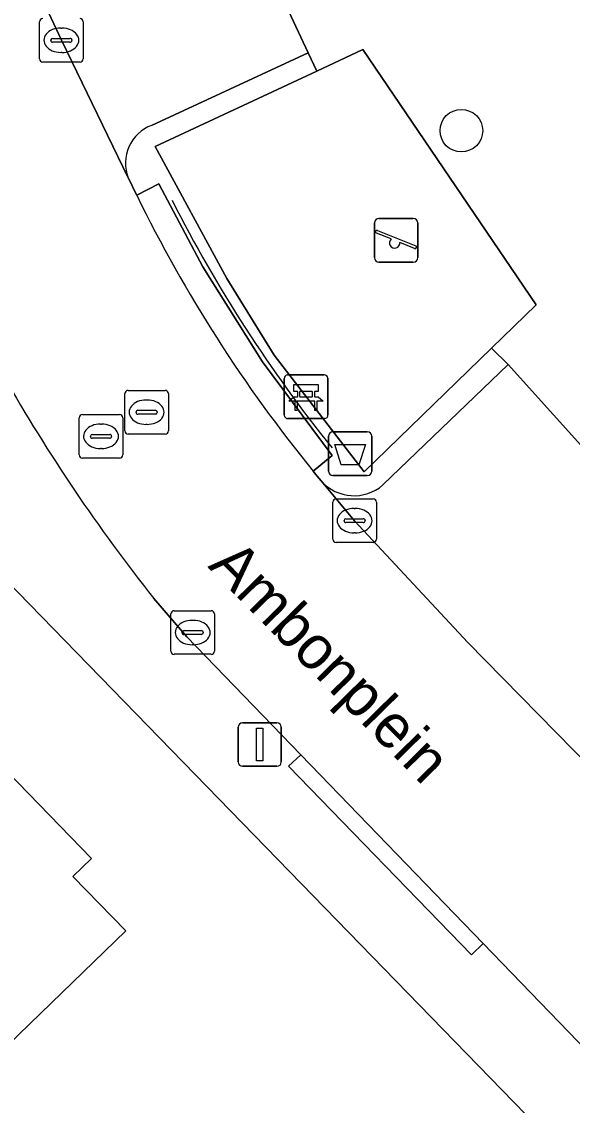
# Model space of a CAD drawing. Extents: x 162879 to 165540, y 384011 to 385181.
# Drawn here: x 163881.82 to 163894.44, y 384275.54 to 384300.4 of the extents above; entities that cross this region are included whole.
import ezdxf

# ---------------------------------------------------------------- set-up
doc = ezdxf.new("R2010")
doc.units = 0
for name, color, linetype in [('IMGEO_Afvalbak', 7, 'Continuous'), ('IMGEO_Bank', 7, 'Continuous'), ('IMGEO_Boom', 7, 'Continuous'), ('IMGEO_Erf', 7, 'Continuous'), ('IMGEO_Groenvoorziening', 7, 'Continuous'), ('IMGEO_Haag', 7, 'Continuous'), ('IMGEO_Hek', 7, 'Continuous'), ('IMGEO_Kolk', 7, 'Continuous'), ('IMGEO_Lichtmast', 7, 'Continuous'), ('IMGEO_Openbare_ruimte_label', 7, 'Continuous'), ('IMGEO_Pand', 7, 'Continuous'), ('IMGEO_Parkeervlak_open', 7, 'Continuous'), ('IMGEO_Rijbaan_lokaal_gesloten', 7, 'Continuous'), ('IMGEO_Rioolput', 7, 'Continuous'), ('IMGEO_Speelvoorziening', 7, 'Continuous'), ('IMGEO_Terreindeel_onvherhard', 7, 'Continuous'), ('IMGEO_Voetpad_open', 7, 'Continuous')]:
    doc.layers.add(name, color=color, linetype=linetype)

msp = doc.modelspace()

# ---------------------------------------------------------------- linework, layer by layer
at = {"layer": 'IMGEO_Afvalbak'}
for p, q in [((163888.855, 384290.09), (163888.855, 384290.89)), ((163888.855, 384290.89), (163888.855, 384290.09)), ((163888.955, 384290.99), (163889.745, 384290.99)), ((163889.745, 384290.99), (163888.955, 384290.99)), ((163889.845, 384290.89), (163889.845, 384290.09)), ((163889.845, 384290.09), (163889.845, 384290.89)), ((163889.745, 384289.99), (163888.955, 384289.99)), ((163888.955, 384289.99), (163889.745, 384289.99))]:
    msp.add_line(p, q, dxfattribs=at)
msp.add_lwpolyline([(163888.998, 384290.704), (163889.702, 384290.704), (163889.553, 384290.234), (163889.147, 384290.234), (163888.998, 384290.704)], dxfattribs=at)
for centre, start, end in [((163888.955, 384290.89), 90, 180), ((163888.955, 384290.89), 90, 180), ((163889.745, 384290.89), 0, 90), ((163889.745, 384290.89), 360, 90), ((163888.955, 384290.09), 180, 270), ((163888.955, 384290.09), 180, 270), ((163889.745, 384290.09), 270, 0), ((163889.745, 384290.09), 270, 0)]:
    msp.add_arc(centre, 0.1, start, end, dxfattribs=at)
at = {"layer": 'IMGEO_Bank'}
for p, q in [((163887.916, 384292.297), (163888.757, 384292.297)), ((163888.757, 384292.297), (163887.916, 384292.297)), ((163887.841, 384291.372), (163887.841, 384292.213)), ((163887.841, 384292.213), (163887.841, 384291.372)), ((163888.841, 384292.222), (163888.841, 384291.381)), ((163888.841, 384291.381), (163888.841, 384292.222)), ((163888.15, 384291.803), (163888.15, 384291.909)), ((163888.194, 384291.909), (163888.194, 384291.803)), ((163888.482, 384291.915), (163888.2, 384291.915)), ((163888.2, 384291.797), (163888.482, 384291.797)), ((163888.488, 384291.803), (163888.488, 384291.909)), ((163888.532, 384291.909), (163888.532, 384291.803)), ((163888.538, 384291.695), (163888.145, 384291.695)), ((163888.766, 384291.297), (163887.925, 384291.297)), ((163887.925, 384291.297), (163888.766, 384291.297))]:
    msp.add_line(p, q, dxfattribs=at)
for points in [[(163888.144, 384291.915), (163888.058, 384291.915), (163888.058, 384292.076), (163888.621, 384292.076), (163888.621, 384291.915), (163888.538, 384291.915)], [(163888.088, 384291.695), (163887.946, 384291.695), (163888.058, 384291.797), (163888.144, 384291.797)], [(163888.538, 384291.797), (163888.621, 384291.797), (163888.733, 384291.695), (163888.594, 384291.695)], [(163888.138, 384291.688), (163888.138, 384291.481), (163888.095, 384291.481), (163888.095, 384291.688)], [(163888.588, 384291.688), (163888.588, 384291.481), (163888.544, 384291.481), (163888.544, 384291.688)]]:
    msp.add_lwpolyline(points, dxfattribs=at)
for centre, radius, start, end in [((163887.919, 384292.219), 0.0779, 92.4484, 184.2845), ((163887.919, 384292.219), 0.0779, 92.4484, 184.2845), ((163888.763, 384292.219), 0.0779, 2.4484, 94.2845), ((163888.763, 384292.219), 0.0779, 2.4484, 94.2845), ((163888.143, 384291.908), 0.00671, 2.8957, 87.1043), ((163888.143, 384291.804), 0.00671, 272.8957, 357.1043), ((163888.2, 384291.908), 0.00671, 92.8957, 177.1043), ((163888.2, 384291.804), 0.00671, 182.8957, 267.1043), ((163888.482, 384291.908), 0.00671, 2.8957, 87.1043), ((163888.482, 384291.804), 0.00671, 272.8957, 357.1043), ((163888.539, 384291.908), 0.00671, 92.8957, 177.1043), ((163888.539, 384291.804), 0.00671, 182.8957, 267.1043), ((163888.088, 384291.688), 0.00671, 2.8957, 87.1043), ((163888.145, 384291.688), 0.00671, 92.8957, 177.1043), ((163888.537, 384291.688), 0.00671, 2.8957, 87.1043), ((163888.594, 384291.688), 0.00671, 92.8957, 177.1043), ((163887.919, 384291.375), 0.0779, 182.4484, 274.2845), ((163887.919, 384291.375), 0.0779, 182.4484, 274.2845), ((163888.763, 384291.375), 0.0779, 272.4484, 4.2845), ((163888.763, 384291.375), 0.0779, 272.4484, 4.2845)]:
    msp.add_arc(centre, radius, start, end, dxfattribs=at)
at = {"layer": 'IMGEO_Boom'}
msp.add_circle((163891.9, 384297.9), 0.489, dxfattribs=at)
at = {"layer": 'IMGEO_Erf'}
for points in [[(163899.33, 384269.205), (163862.239, 384307.377)], [(163852.36, 384301.956), (163854.02, 384301.957), (163856.929, 384300.707), (163859.847, 384299.453), (163861.001, 384298.26), (163864.034, 384301.194), (163868.122, 384296.969), (163871.022, 384293.972), (163870.6, 384293.562), (163871.811, 384292.314), (163867.394, 384288.028), (163869.463, 384285.896), (163871.58, 384283.715), (163875.993, 384287.998), (163877.197, 384286.756), (163877.627, 384287.173), (163880.526, 384284.185), (163883.421, 384281.202), (163882.999, 384280.792), (163884.207, 384279.548), (163879.797, 384275.268)]]:
    msp.add_lwpolyline(points, dxfattribs=at)
at = {"layer": 'IMGEO_Groenvoorziening'}
msp.add_lwpolyline([(163888.505, 384290.088), (163888.943, 384290.447), (163887.341, 384292.596), (163885.974, 384294.779), (163884.964, 384296.677), (163884.46, 384296.42)], dxfattribs=at)
msp.add_arc((163914.001, 384310.833), 32.87, 206.0082, 219.1342, dxfattribs=at)
at = {"layer": 'IMGEO_Haag'}
msp.add_lwpolyline([(163888.505, 384290.088), (163888.943, 384290.447), (163887.341, 384292.596), (163885.974, 384294.779), (163884.964, 384296.677), (163884.46, 384296.42)], dxfattribs=at)
msp.add_arc((163914.001, 384310.833), 32.87, 206.0082, 219.1342, dxfattribs=at)
at = {"layer": 'IMGEO_Hek'}
msp.add_arc((163914.208, 384310.967), 32.442, 206.8705, 218.8312, dxfattribs=at)
at = {"layer": 'IMGEO_Kolk'}
for p, q in [((163882.233, 384299.548), (163882.233, 384300.4)), ((163882.721, 384300.254), (163882.746, 384300.254)), ((163883.234, 384300.4), (163883.234, 384299.548)), ((163882.535, 384300.017), (163882.933, 384300.017)), ((163882.492, 384299.968), (163882.492, 384299.98)), ((163882.93, 384299.931), (163882.532, 384299.931)), ((163882.976, 384299.98), (163882.976, 384299.968)), ((163882.744, 384299.694), (163882.719, 384299.694)), ((163883.16, 384299.474), (163882.308, 384299.474)), ((163888.953, 384288.528), (163888.953, 384289.38)), ((163889.028, 384289.454), (163889.88, 384289.454)), ((163889.954, 384289.38), (163889.954, 384288.528)), ((163889.441, 384289.234), (163889.466, 384289.234)), ((163889.212, 384288.948), (163889.212, 384288.96)), ((163889.65, 384288.911), (163889.252, 384288.911)), ((163889.255, 384288.997), (163889.653, 384288.997)), ((163889.696, 384288.96), (163889.696, 384288.948)), ((163889.464, 384288.674), (163889.439, 384288.674)), ((163889.88, 384288.454), (163889.028, 384288.454)), ((163885.242, 384285.962), (163885.242, 384286.814)), ((163885.317, 384286.888), (163886.169, 384286.888)), ((163886.243, 384286.814), (163886.243, 384285.962)), ((163885.73, 384286.668), (163885.755, 384286.668)), ((163885.501, 384286.382), (163885.501, 384286.394)), ((163885.939, 384286.345), (163885.541, 384286.345)), ((163885.544, 384286.431), (163885.942, 384286.431)), ((163885.985, 384286.394), (163885.985, 384286.382)), ((163885.753, 384286.108), (163885.728, 384286.108)), ((163886.169, 384285.888), (163885.317, 384285.888))]:
    msp.add_line(p, q, dxfattribs=at)
for points in [[(163882.233, 384299.548), (163882.233, 384300.4)], [(163883.234, 384300.4), (163883.234, 384299.548)], [(163883.16, 384299.474), (163882.308, 384299.474)], [(163888.953, 384288.528), (163888.953, 384289.38)], [(163889.028, 384289.454), (163889.88, 384289.454)], [(163889.954, 384289.38), (163889.954, 384288.528)], [(163889.88, 384288.454), (163889.028, 384288.454)], [(163885.242, 384285.962), (163885.242, 384286.814)], [(163885.317, 384286.888), (163886.169, 384286.888)], [(163886.243, 384286.814), (163886.243, 384285.962)], [(163886.169, 384285.888), (163885.317, 384285.888)]]:
    msp.add_lwpolyline(points, dxfattribs=at)
for centre, radius, start, end in [((163882.31, 384300.398), 0.0765, 91.552, 178.448), ((163882.31, 384300.398), 0.0765, 91.552, 178.448), ((163883.158, 384300.398), 0.0765, 1.552, 88.448), ((163883.158, 384300.398), 0.0765, 1.552, 88.448), ((163882.532, 384299.977), 0.0403, 85.8775, 175.7526), ((163882.937, 384299.979), 0.0386, 1.7309, 96.639), ((163882.529, 384299.967), 0.0366, 178.938, 274.7102), ((163882.933, 384299.974), 0.043, 264.8664, 352.4533), ((163882.31, 384299.55), 0.0765, 181.552, 268.448), ((163882.31, 384299.55), 0.0765, 181.552, 268.448), ((163883.158, 384299.55), 0.0765, 271.552, 358.448), ((163883.158, 384299.55), 0.0765, 271.552, 358.448), ((163889.03, 384289.378), 0.0765, 91.552, 178.448), ((163889.03, 384289.378), 0.0765, 91.552, 178.448), ((163889.878, 384289.378), 0.0765, 1.552, 88.448), ((163889.878, 384289.378), 0.0765, 1.552, 88.448), ((163889.252, 384288.957), 0.0403, 85.8775, 175.7526), ((163889.249, 384288.947), 0.0366, 178.938, 274.7102), ((163889.653, 384288.954), 0.043, 264.8664, 352.4533), ((163889.657, 384288.959), 0.0386, 1.7309, 96.639), ((163889.03, 384288.53), 0.0765, 181.552, 268.448), ((163889.03, 384288.53), 0.0765, 181.552, 268.448), ((163889.878, 384288.53), 0.0765, 271.552, 358.448), ((163889.878, 384288.53), 0.0765, 271.552, 358.448), ((163885.319, 384286.812), 0.0765, 91.552, 178.448), ((163885.319, 384286.812), 0.0765, 91.552, 178.448), ((163886.167, 384286.812), 0.0765, 1.552, 88.448), ((163886.167, 384286.812), 0.0765, 1.552, 88.448), ((163885.541, 384286.391), 0.0403, 85.8775, 175.7526), ((163885.538, 384286.381), 0.0366, 178.938, 274.7102), ((163885.942, 384286.388), 0.043, 264.8664, 352.4533), ((163885.946, 384286.393), 0.0386, 1.7309, 96.639), ((163885.319, 384285.964), 0.0765, 181.552, 268.448), ((163885.319, 384285.964), 0.0765, 181.552, 268.448), ((163886.167, 384285.964), 0.0765, 271.552, 358.448), ((163886.167, 384285.964), 0.0765, 271.552, 358.448)]:
    msp.add_arc(centre, radius, start, end, dxfattribs=at)
for centre, major_axis, ratio, start_param, end_param in [((163882.72, 384299.974), (-0.387, 0.002), 0.722429, 4.712389, 7.853982), ((163882.745, 384299.974), (-0.39, 0.002), 0.717154, 1.570796, 4.712389), ((163889.44, 384288.954), (-0.387, 0.002), 0.722429, 4.712389, 7.853982), ((163889.465, 384288.954), (-0.39, 0.002), 0.717154, 1.570796, 4.712389), ((163885.729, 384286.388), (-0.387, 0.002), 0.722429, 4.712389, 7.853982), ((163885.754, 384286.388), (-0.39, 0.002), 0.717154, 1.570796, 4.712389)]:
    msp.add_ellipse(centre, major_axis=major_axis, ratio=ratio, start_param=start_param, end_param=end_param, dxfattribs=at)
at = {"layer": 'IMGEO_Lichtmast'}
for p, q in [((163886.783, 384283.419), (163886.783, 384284.219)), ((163886.783, 384284.219), (163886.783, 384283.419)), ((163886.883, 384284.319), (163887.673, 384284.319)), ((163887.673, 384284.319), (163886.883, 384284.319)), ((163887.773, 384284.219), (163887.773, 384283.419)), ((163887.773, 384283.419), (163887.773, 384284.219)), ((163887.673, 384283.319), (163886.883, 384283.319)), ((163886.883, 384283.319), (163887.673, 384283.319))]:
    msp.add_line(p, q, dxfattribs=at)
msp.add_lwpolyline([(163887.203, 384284.194), (163887.353, 384284.194), (163887.353, 384283.444), (163887.203, 384283.444), (163887.203, 384284.194)], dxfattribs=at)
for centre, start, end in [((163886.883, 384284.219), 90, 180), ((163886.883, 384284.219), 90, 180), ((163887.673, 384284.219), 0, 90), ((163887.673, 384284.219), 360, 90), ((163886.883, 384283.419), 180, 270), ((163886.883, 384283.419), 180, 270), ((163887.673, 384283.419), 270, 0), ((163887.673, 384283.419), 270, 0)]:
    msp.add_arc(centre, 0.1, start, end, dxfattribs=at)
at = {"layer": 'IMGEO_Pand'}
msp.add_lwpolyline([(163872.435, 384276.367), (163876.307, 384272.378), (163874.635, 384270.755), (163876.963, 384268.356), (163881.884, 384273.118), (163879.797, 384275.268), (163884.207, 384279.548), (163882.999, 384280.792), (163883.421, 384281.202), (163880.526, 384284.185)], close=True, dxfattribs=at)
at = {"layer": 'IMGEO_Parkeervlak_open'}
for points in [[(163884.802, 384298.021), (163888.388, 384299.683), (163882.043, 384313.266), (163878.44, 384311.595)], [(163877.096, 384312.046), (163878.002, 384310.066), (163882.733, 384299.973), (163884.265, 384296.82)], [(163898.767, 384280.751), (163901.634, 384283.506), (163895.053, 384290.227), (163892.97, 384292.54), (163890.101, 384289.773)], [(163888.687, 384289.866), (163889.454, 384288.953), (163892.052, 384286.156), (163897.301, 384280.799), (163898.746, 384279.314)]]:
    msp.add_lwpolyline(points, dxfattribs=at)
for centre, radius, start, end in [((163885.125, 384297.156), 0.923, 110.4568, 201.3617), ((163889.441, 384290.535), 1.008, 221.5633, 310.9107)]:
    msp.add_arc(centre, radius, start, end, dxfattribs=at)
at = {"layer": 'IMGEO_Rijbaan_lokaal_gesloten'}
for points in [[(163884.46, 384296.42), (163884.395, 384296.553), (163884.331, 384296.686), (163884.265, 384296.82), (163882.733, 384299.973), (163878.002, 384310.066), (163877.096, 384312.046), (163876.805, 384312.696)], [(163899.806, 384278.207), (163898.746, 384279.314), (163897.301, 384280.799), (163892.052, 384286.156), (163889.454, 384288.953), (163888.687, 384289.866), (163888.596, 384289.977), (163888.505, 384290.088)], [(163884.85, 384287.172), (163885.611, 384286.288), (163888.22, 384283.584), (163892.399, 384279.255), (163900.23, 384271.142), (163903.359, 384267.9), (163903.727, 384267.518), (163912.083, 384275.609), (163924.617, 384287.795), (163925.486, 384288.61)]]:
    msp.add_lwpolyline(points, dxfattribs=at)
for centre, radius, start, end in [((163914.001, 384310.833), 32.87, 206.0082, 219.1342), ((163916.349, 384312.121), 40.183, 209.6097, 218.3807)]:
    msp.add_arc(centre, radius, start, end, dxfattribs=at)
at = {"layer": 'IMGEO_Rioolput'}
for p, q in [((163884.186, 384291.016), (163884.186, 384291.868)), ((163884.261, 384291.942), (163885.113, 384291.942)), ((163885.187, 384291.868), (163885.187, 384291.016)), ((163884.674, 384291.722), (163884.699, 384291.722)), ((163883.141, 384290.464), (163883.141, 384291.316)), ((163883.216, 384291.39), (163884.068, 384291.39)), ((163884.142, 384291.316), (163884.142, 384290.464)), ((163884.445, 384291.436), (163884.445, 384291.448)), ((163884.883, 384291.399), (163884.485, 384291.399)), ((163884.488, 384291.485), (163884.886, 384291.485)), ((163884.929, 384291.448), (163884.929, 384291.436)), ((163883.629, 384291.17), (163883.654, 384291.17)), ((163884.697, 384291.162), (163884.672, 384291.162)), ((163883.4, 384290.884), (163883.4, 384290.896)), ((163883.838, 384290.847), (163883.44, 384290.847)), ((163883.443, 384290.933), (163883.841, 384290.933)), ((163883.884, 384290.896), (163883.884, 384290.884)), ((163885.113, 384290.942), (163884.261, 384290.942)), ((163883.652, 384290.61), (163883.627, 384290.61)), ((163884.068, 384290.39), (163883.216, 384290.39))]:
    msp.add_line(p, q, dxfattribs=at)
for points in [[(163884.186, 384291.016), (163884.186, 384291.868)], [(163884.261, 384291.942), (163885.113, 384291.942)], [(163885.187, 384291.868), (163885.187, 384291.016)], [(163883.141, 384290.464), (163883.141, 384291.316)], [(163883.216, 384291.39), (163884.068, 384291.39)], [(163884.142, 384291.316), (163884.142, 384290.464)], [(163885.113, 384290.942), (163884.261, 384290.942)], [(163884.068, 384290.39), (163883.216, 384290.39)]]:
    msp.add_lwpolyline(points, dxfattribs=at)
for centre, radius, start, end in [((163884.263, 384291.866), 0.0765, 91.552, 178.448), ((163884.263, 384291.866), 0.0765, 91.552, 178.448), ((163885.111, 384291.866), 0.0765, 1.552, 88.448), ((163885.111, 384291.866), 0.0765, 1.552, 88.448), ((163883.218, 384291.314), 0.0765, 91.552, 178.448), ((163883.218, 384291.314), 0.0765, 91.552, 178.448), ((163884.066, 384291.314), 0.0765, 1.552, 88.448), ((163884.066, 384291.314), 0.0765, 1.552, 88.448), ((163884.485, 384291.445), 0.0403, 85.8775, 175.7526), ((163884.482, 384291.435), 0.0366, 178.938, 274.7102), ((163884.886, 384291.442), 0.043, 264.8664, 352.4533), ((163884.89, 384291.447), 0.0386, 1.7309, 96.639), ((163883.44, 384290.893), 0.0403, 85.8775, 175.7526), ((163883.437, 384290.883), 0.0366, 178.938, 274.7102), ((163883.841, 384290.89), 0.043, 264.8664, 352.4533), ((163883.845, 384290.895), 0.0386, 1.7309, 96.639), ((163884.263, 384291.018), 0.0765, 181.552, 268.448), ((163884.263, 384291.018), 0.0765, 181.552, 268.448), ((163885.111, 384291.018), 0.0765, 271.552, 358.448), ((163885.111, 384291.018), 0.0765, 271.552, 358.448), ((163883.218, 384290.466), 0.0765, 181.552, 268.448), ((163883.218, 384290.466), 0.0765, 181.552, 268.448), ((163884.066, 384290.466), 0.0765, 271.552, 358.448), ((163884.066, 384290.466), 0.0765, 271.552, 358.448)]:
    msp.add_arc(centre, radius, start, end, dxfattribs=at)
for centre, major_axis, ratio, start_param, end_param in [((163884.673, 384291.442), (-0.387, 0.002), 0.722429, 4.712389, 7.853982), ((163884.698, 384291.442), (-0.39, 0.002), 0.717154, 1.570796, 4.712389), ((163883.628, 384290.89), (-0.387, 0.002), 0.722429, 4.712389, 7.853982), ((163883.653, 384290.89), (-0.39, 0.002), 0.717154, 1.570796, 4.712389)]:
    msp.add_ellipse(centre, major_axis=major_axis, ratio=ratio, start_param=start_param, end_param=end_param, dxfattribs=at)
at = {"layer": 'IMGEO_Speelvoorziening'}
for p, q in [((163889.909, 384294.987), (163889.909, 384295.787)), ((163889.909, 384295.787), (163889.909, 384294.987)), ((163890.009, 384295.887), (163890.799, 384295.887)), ((163890.799, 384295.887), (163890.009, 384295.887)), ((163890.899, 384295.787), (163890.899, 384294.987)), ((163890.899, 384294.987), (163890.899, 384295.787)), ((163890.292, 384295.415), (163889.953, 384295.552)), ((163889.978, 384295.612), (163890.854, 384295.259)), ((163890.83, 384295.199), (163890.49, 384295.336)), ((163890.799, 384294.887), (163890.009, 384294.887)), ((163890.009, 384294.887), (163890.799, 384294.887))]:
    msp.add_line(p, q, dxfattribs=at)
for centre, radius, start, end in [((163890.009, 384295.787), 0.1, 90, 180), ((163890.009, 384295.787), 0.1, 90, 180), ((163890.799, 384295.787), 0.1, 0, 90), ((163890.799, 384295.787), 0.1, 360, 90), ((163889.966, 384295.582), 0.0327, 68.078, 248.078), ((163890.371, 384295.325), 0.12, 130.9928, 5.1632), ((163890.842, 384295.229), 0.0327, 248.078, 68.078), ((163890.009, 384294.987), 0.1, 180, 270), ((163890.009, 384294.987), 0.1, 180, 270), ((163890.799, 384294.987), 0.1, 270, 0), ((163890.799, 384294.987), 0.1, 270, 0)]:
    msp.add_arc(centre, radius, start, end, dxfattribs=at)
at = {"layer": 'IMGEO_Terreindeel_onvherhard'}
msp.add_lwpolyline([(163889.645, 384299.764), (163888.585, 384299.268), (163884.882, 384297.537), (163886.529, 384294.51), (163887.608, 384292.747), (163889.67, 384290.076), (163892.593, 384292.912), (163893.617, 384293.905)], close=True, dxfattribs=at)
at = {"layer": 'IMGEO_Voetpad_open'}
for points in [[(163878.44, 384311.595), (163882.043, 384313.266), (163888.388, 384299.683), (163888.585, 384299.268), (163889.645, 384299.764), (163893.617, 384293.905), (163892.593, 384292.912), (163892.97, 384292.54), (163895.053, 384290.227), (163901.634, 384283.506), (163898.767, 384280.751)], [(163862.239, 384307.377), (163899.33, 384269.205)], [(163892.97, 384292.54), (163892.593, 384292.912), (163889.67, 384290.076), (163887.608, 384292.747), (163886.529, 384294.51), (163884.882, 384297.537), (163888.585, 384299.268), (163888.388, 384299.683), (163884.802, 384298.021)], [(163884.265, 384296.82), (163884.331, 384296.686), (163884.395, 384296.553), (163884.46, 384296.42), (163884.964, 384296.677), (163885.974, 384294.779), (163887.341, 384292.596), (163888.943, 384290.447), (163888.505, 384290.088), (163888.596, 384289.977), (163888.687, 384289.866)], [(163890.101, 384289.773), (163892.97, 384292.54)], [(163899.118, 384264.928), (163903.137, 384267.681), (163899.988, 384270.921), (163900.23, 384271.142), (163892.399, 384279.255), (163892.135, 384278.994), (163887.94, 384283.319), (163888.22, 384283.584), (163885.611, 384286.288), (163884.85, 384287.172)]]:
    msp.add_lwpolyline(points, dxfattribs=at)
msp.add_lwpolyline([(163888.22, 384283.584), (163887.94, 384283.319), (163892.135, 384278.994), (163892.399, 384279.255)], close=True, dxfattribs=at)
for centre, radius, start, end in [((163885.125, 384297.156), 0.923, 110.4568, 201.3617), ((163916.349, 384312.121), 40.183, 209.6097, 218.3807), ((163889.441, 384290.535), 1.008, 221.5633, 310.9107)]:
    msp.add_arc(centre, radius, start, end, dxfattribs=at)

# ---------------------------------------------------------------- texts
at = {"layer": 'IMGEO_Openbare_ruimte_label'}
msp.add_text('Ambonplein', height=1, rotation=314.5138, dxfattribs=at).set_placement((163886.073, 384287.897))

doc.saveas('drawing.dxf')
